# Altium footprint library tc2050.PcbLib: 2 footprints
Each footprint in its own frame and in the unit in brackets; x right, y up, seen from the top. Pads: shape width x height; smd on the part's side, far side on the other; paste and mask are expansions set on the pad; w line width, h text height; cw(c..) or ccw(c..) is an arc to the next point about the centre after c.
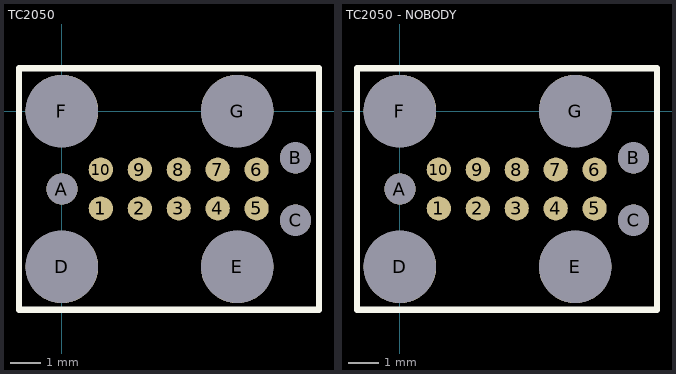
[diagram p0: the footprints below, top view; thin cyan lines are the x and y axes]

## TC2050 [mil] "TAG CONNECT PLUG  OF NAILS VICTIM AND PLUG BODY"
pads (17):
  round 31 smd paste-40: 1(50,-125) 2(100,-125) 3(150,-125) 4(200,-125) 5(250,-125) 6(250,-75) 7(200,-75) 8(150,-75) 9(100,-75) 10(50,-75)
  round 40 hole 40 unplated: A(0,-100) B(300,-60) C(300,-140)
  round 93 hole 93 unplated: D(0,-200) E(225,-200) F(0,0) G(225,0)
Top Overlay:
  lines w7.87: -55,-255 -55,55 330,55 330,-255 -55,-255
3D body: height 1177.83, standoff -172.07, extent -110,-286.86 390,86.85

## TC2050 - NOBODY [mil] "TAG CONNECT PLUG OF NAILS VICTIM"
pads (17):
  round 31 smd paste-40: 1(50,-125) 2(100,-125) 3(150,-125) 4(200,-125) 5(250,-125) 6(250,-75) 7(200,-75) 8(150,-75) 9(100,-75) 10(50,-75)
  round 40 hole 40 unplated: A(0,-100) B(300,-60) C(300,-140)
  round 93 hole 93 unplated: D(0,-200) E(225,-200) F(0,0) G(225,0)
Top Overlay:
  lines w7.87: -55,-255 330,-255 330,55 -55,55 -55,-255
